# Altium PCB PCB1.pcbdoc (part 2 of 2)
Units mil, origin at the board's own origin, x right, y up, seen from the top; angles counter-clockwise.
Board outline 3200 x 1800 mil, 2 copper layers (Top Layer, Bottom Layer), stack 62.206 mil thick; 104 components, 97 nets, 542 pads, 186 vias.
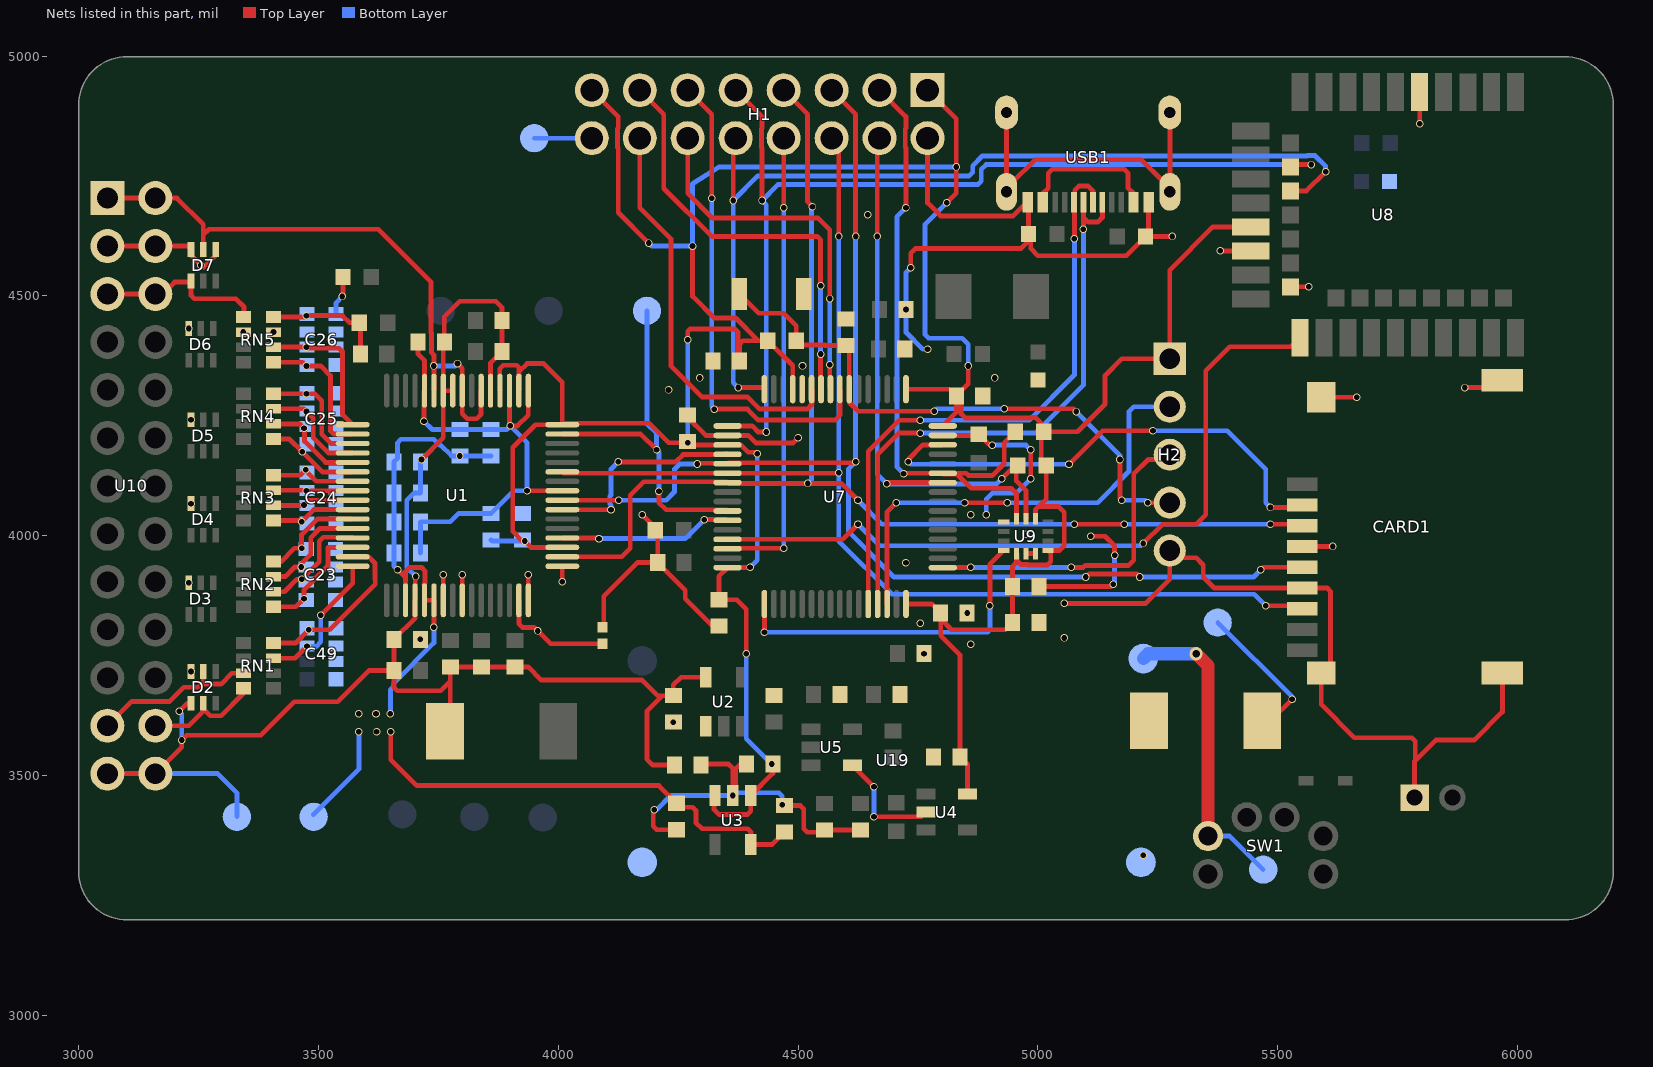
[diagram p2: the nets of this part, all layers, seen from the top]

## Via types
v1: diameter 15.75, hole 11.8, Top Layer to Bottom Layer, 184 vias
v2: diameter 19.68, hole 13.8, Top Layer to Bottom Layer, 1 vias
v3: diameter 27.56, hole 15.7, Top Layer to Bottom Layer, 1 vias

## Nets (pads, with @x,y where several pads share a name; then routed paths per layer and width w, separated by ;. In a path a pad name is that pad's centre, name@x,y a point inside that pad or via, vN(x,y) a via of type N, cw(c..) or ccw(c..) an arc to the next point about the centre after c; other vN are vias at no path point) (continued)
AGND: C5.1 C6.2 C11.1 C12.1 C13.2 C14.1 C15.1 C16.1 C17.1 C18.1 C19.1 C21.1 C22.1 C23.5 C23.6 C23.7 C23.8 C24.5 C24.6 C24.7 C24.8 C25.5 C25.6 C25.7 C25.8 C26.3 C26.5 C26.6 C26.7 C26.8 C29.1 C30.1 C31.1 C32.1 C33.1 C34.1 C49.5 C49.6 C49.7 C49.8 D2.3 D3.3 D4.3 D5.3 D6.3 D7.1 D7.3 R1.2 R13.1 RN5.2 RN5.7 U1.31 U1.33 U1.41 U1.49 U1.51 U1.60 U2.1 U3.2 U4.2 U5.4 U10.3 U10.4 U19.4 | length 2732.8
  Top Layer w10: U10.3@3060,4603.82 U10.4@3160,4603.82 3227.48,4603.82 D7.3@3234.41,4596.89 3234.41,4584.41 v1(3255,4563.82) ; v1@3260,4558.82 3285.59,4584.41 D7.1@3285.59,4596.89 ; v1(3550,4498.82) 3551.02,4499.84 R1.2@3551.02,4539.5 ; C6.2@3707.44,4393.82 3707.44,4379.47 3721.1,4365.81 U1.60@3721.1,4302.32 3720,4301.22 v1(3720,4238.82) ; U1.51@3898.27,4302.32 3898.27,4230.55 v1(3900,4228.82) 3915,4228.82 3937.5,4251.32 3937.5,4302.18 U1.49@3937.64,4302.32 ; U1.31@3917.95,3865.32 3917.95,3816.31 3925.44,3808.82 3950,3808.82 v1(3957.5,3801.32) 3984.08,3774.74 R13.1@4092.04,3774.74 ; v1(3935,4093.82) 3944.84,4093.82 3945,4093.66 U1.41@4008.5,4093.66 ; v1(4008.5,3903.82) U1.33@4008.5,3936.18 ; v1(4200,3428.82) 4197.93,3426.74 4197.93,3394.01 4205,3386.93 C16.1@4246.76,3386.93 ; C12.1@4297.57,3521.68 4299.7,3523.82 4355,3523.82 4364.2,3514.61 v1(4364.2,3458.24) 4370,3464.04 4370,3513.82 4380,3523.82 C17.1@4392.44,3523.82 ; C15.1@4471.76,3437.17 4505,3437.17 4512.07,3430.1 4512.07,3388.82 4519.14,3381.74 4550.49,3381.74 C21.1@4555,3386.26 C18.1@4630,3386.26 ; U5.4@4613.31,3521.41 v1(4658.23,3476.49) ; v1(4658.23,3413.82) 4756.69,3413.82 U4.2@4766.69,3423.82
  Bottom Layer w10: C26.5@3536.79,4461.97 3536.79,4485.6 v1(3550,4498.82) ; C32.1@3712.56,3963.82 C31.1@3712.56,4028.82 3775,4028.82 3792.56,4046.38 C29.1@3860,4046.38 3907.44,4093.82 v1(3935,4093.82) 3935,4193.82 v1(3900,4228.82) 3892.56,4221.38 C33.1@3860,4221.38 C34.1@3795,4221.38 3737.44,4221.38 v1(3720,4238.82) ; v1(4200,3428.82) 4205,3428.82 4234.42,3458.24 v1(4364.2,3458.24) 4369.78,3463.82 4460,3463.82 4467.07,3456.74 v1(4467.07,3438.82) ; v1(4658.23,3413.82) v1(4658.23,3476.49)
  other v1: 4240,3611.26 3234.41,3716.89 3712.56,3783.82 3229.41,3901.89 3234.41,4066.89 3234.41,4241.89 3343.5,4424.57 3406.5,4424.57 3229.41,4431.89
AVDD: AVDD.1 C15.2 C16.2 C27.2 C28.2 C31.2 C32.2 C33.2 C34.2 D7.2 U1.19 U1.21 U1.22 U1.54 U1.56 U1.59 U3.5 U10.1 U10.2 | length 3427.8
  Top Layer w10: U10.1@3060,4703.82 U10.2@3160,4703.82 3205,4703.82 3260,4648.82 3260,4626.95 ; D7.2@3260,4596.89 3260,4626.95 ; v1(3650.67,3591.06) 3650.67,3533.14 3705,3478.82 4210,3478.82 C16.2@4246.76,3442.05 4255,3433.82 4280,3433.82 4287.07,3426.74 4287.07,3401.74 4300,3388.82 4395,3388.82 4402.07,3381.74 4402.07,3356.34 U3.5@4401.6,3355.87 4445.58,3355.87 C15.2@4471.76,3382.05 ; v1(3665,3928.82) 3681.73,3912.09 ; U1.19@3681.73,3865.32 3681.73,3912.09 ; U1.21@3720,3898.82 3722.07,3900.89 3722.07,3926.74 3715,3933.82 3690,3933.82 3681.73,3925.55 3681.73,3912.09 ; U1.21@3721.1,3865.32 U1.22@3740.79,3865.32 v1(3740.79,3808.82) ; U1.59@3740.79,4302.32 v1(3740.79,4353.82) 3740.79,4376.59 3735.83,4381.55 3735.83,4422.99 3735,4423.82 3735,4528.82 3625,4638.82 3271.86,4638.82 3260,4626.95 ; v1(3790,4358.82) 3799.84,4348.98 U1.56@3799.84,4302.32 3799.84,4253.98 3810,4243.82 3830,4243.82 3839.21,4253.03 U1.54@3839.21,4302.32
  Bottom Layer w10: AVDD.1@3490,3418.82 3584.37,3513.18 v1(3584.37,3591.06) ; v1(3650,3628.82) 3650,3678.82 3657.01,3685.82 3657.01,3692.49 3740.79,3776.28 v1(3740.79,3808.82) ; v1(3665,3928.82) 3657.44,3936.38 C32.2@3657.44,3963.82 C31.2@3657.44,4028.82 C28.2@3657.44,4088.82 C27.2@3657.44,4153.82 3665,4161.38 3665,4193.82 3672.07,4200.89 3740,4200.89 3752.07,4188.82 3755,4188.82 3777.56,4166.26 v1(3795,4166.26) C33.2@3860,4166.26 ; v1(3740.79,4353.82) 3785,4353.82 v1(3790,4358.82)
  other v1: 3621.15,3591.06 3584.37,3628.82 3620,3628.82
AVSS: AVSS.1 C1.1 C2.1 C3.2 C4.2 C5.2 C6.1 C7.1 C8.1 C9.1 C12.2 C13.1 C27.1 C28.1 D2.4 U1.20 U1.23 U1.25 U1.32 U1.53 U1.57 U1.58 U2.5 U10.25 U10.26 | length 3424.3
  Top Layer w10: U10.25@3060,3503.82 U10.26@3160,3503.82 3215,3558.82 v1(3215,3573.82) 3225,3583.82 3380,3583.82 3450,3653.82 3540,3653.82 3605,3718.82 C9.1@3657.44,3718.82 ; v1(3210,3633.82) 3226.93,3650.75 D2.4@3234.41,3650.75 ; v1(3702.6,3914.96) 3702.01,3914.37 3702.01,3891.36 3702.6,3890.77 3702.6,3866.49 U1.20@3701.42,3865.32 3701.42,3827.8 C5.2@3657.44,3783.82 C9.1@3657.44,3718.82 ; v1(3715,4158.82) 3760.47,4204.29 U1.58@3760.47,4302.32 ; U1.23@3760.47,3865.32 v1(3760.47,3918.82) ; C1.1@3763.78,3591.93 3775,3603.15 3775,3696.74 ; U1.57@3780.16,4302.32 U1.58@3760.47,4302.32 ; U1.25@3799.84,3865.32 3800,3865.48 v1(3800,3918.82) ; U1.53@3858.9,4302.32 3858.9,4360.16 C4.2@3882.56,4383.82 C3.2@3882.56,4448.82 3882.56,4476.26 3870,4488.82 3795,4488.82 3762.56,4456.38 3762.56,4393.82 3760.47,4391.73 U1.58@3760.47,4302.32 ; U1.32@3937.64,3865.32 v1(3937.64,3918.82) ; C12.2@4242.45,3521.68 4197.14,3521.68 4185,3533.82 4185,3634.2 4217.18,3666.38 ; U2.5@4307.6,3705 4256.19,3705 4240,3688.82 C13.1@4240,3666.38 4217.18,3666.38 ; C9.1@3657.44,3718.82 3657.44,3683.82 3664.51,3676.74 3755,3676.74 3775,3696.74 ; 3775,3696.74 C7.1@3775,3726.26 C8.1@3840,3726.26 C2.1@3910,3726.26 3937.56,3726.26 3965,3698.82 4175,3698.82 4207.44,3666.38 4217.18,3666.38
  Bottom Layer w10: U10.26@3160,3503.82 3290,3503.82 3330,3463.82 AVSS.1@3330,3413.82 ; v1(3210,3633.82) 3215,3628.82 v1(3215,3573.82) ; v1(3702.6,3914.96) 3684.17,3933.38 3684.17,4073.82 3699.17,4088.82 C28.1@3712.56,4088.82 C27.1@3712.56,4153.82
BIAS: D7.4 RN5.1 U10.5 U10.6 | length 343.9
  Top Layer w10: U10.5@3060,4503.82 U10.6@3160,4503.82 3175,4503.82 3200,4528.82 3232.48,4528.82 D7.4@3234.41,4530.75 3234.41,4500.89 3241.48,4493.82 3327.93,4493.82 3345,4476.74 RN5.1@3345,4468.82
BIAS_DRV: C10.2 C26.4 R2.2 RN5.8 | length 252.1
  Top Layer w10: RN5.8@3406.5,4456.06 3472.24,4456.06 v1(3475,4458.82) 3550,4458.82 3565,4443.82 R2.2@3585.34,4443.82 3587.44,4441.72 C10.2@3587.44,4378.82
CS1: U1.39 U7.20 | length 444.9
  Top Layer w10: U1.39@4008.5,4054.29 4008.97,4053.82 v1(4110,4053.82) ; v1(4125,4153.82) 4245,4153.82 4260.19,4169.01 4346.63,4169.01 4347.76,4170.14 U7.20@4353.01,4170.14
  Bottom Layer w10: v1(4110,4053.82) 4110,4063.45 4107.28,4066.16 4107.28,4081.79 4110,4084.5 4110,4138.82 v1(4125,4153.82)
CS2: CARD1.2 U7.62 | length 1051.3
  Top Layer w10: v1(4730,4153.82) 4730,4158.82 4760.5,4189.32 U7.62@4801.83,4189.32 ; v1(5065,4148.82) 5135,4218.82 v1(5240,4218.82) ; v1(5485,4058.82) 5546.06,4058.82 CARD1.2@5551.34,4064.1
  Bottom Layer w10: v1(4730,4153.82) 4735,4148.82 v1(5065,4148.82) ; v1(5240,4218.82) 5395,4218.82 5475,4138.82 5475,4068.82 v1(5485,4058.82)
CS3: H1.8 U7.30 | length 972.4
  Top Layer w10: U7.30@4353.01,3972.78 4354.05,3973.82 v1(4470,3973.82) ; v1(4470,4683.82) H1.8@4470,4828.82
  Bottom Layer w10: v1(4470,3973.82) v1(4470,4683.82)
D+: U7.44 USB1.A6 USB1.B6 | length 1269.2
  Top Layer w10: U7.44@4646.32,3857.57 4646.32,4175.59 4711.29,4240.55 v1(4755,4240.55) ; v1(5076.14,4618.82) 5076.14,4694.64 USB1.B6@5075.47,4695.31 5077.01,4696.84 5077.01,4720.26 5085.57,4728.82 5105,4728.82 5114.85,4718.97 USB1.A6@5114.84,4695.31
  Bottom Layer w10: v1(4755,4240.55) 4981.73,4240.55 5076.14,4334.96 v1(5076.14,4618.82)
D-: U7.45 USB1.A7 USB1.B7 | length 1262
  Top Layer w10: U7.45@4666,3857.57 4666,4169.82 4710,4213.82 v1(4755,4213.82) ; v1(5095,4638.82) 5095,4663.82 ; USB1.A7@5095.15,4695.31 5095,4695.16 5095,4663.82 ; USB1.B7@5134.52,4695.31 5134.52,4663.34 5125,4653.82 5105,4653.82 5095,4663.82
  Bottom Layer w10: v1(4755,4213.82) 4995,4213.82 5095,4313.82 v1(5095,4638.82)
DRDY: TP_DRDY.1 U1.47 U7.26 | length 767.4
  Top Layer w10: U1.47@4008.5,4211.77 4172.05,4211.77 v1(4205,4178.82) ; v1(4210,4092.83) 4210,4068.82 4225,4053.82 U7.26@4350.72,4053.82
  Bottom Layer w10: TP_DRDY.1@4185,4468.82 4185,4233.82 4205,4213.82 v1(4205,4178.82) 4210,4173.82 v1(4210,4092.83)
DVDD: C17.2 C19.2 C29.2 C30.2 C40.2 C41.2 C42.2 C43.1 C44.1 C45.1 C46.1 C47.2 CARD1.4 DVDD.1 H1.1 H1.15 H2.1 R4.2 R9.2 R10.2 U1.35 U1.48 U1.50 U1.52 U3.1 U3.3 U4.5 U7.1 U7.13 U7.19 U7.32 U7.48 U7.64 U8.19 U9.5 U9.8 U9.12 | length 7907.1
  Top Layer w10: U1.52@3878.58,4302.32 3877.93,4302.97 3877.93,4348.04 3885,4355.12 3913.7,4355.12 3917.95,4350.87 3917.95,4341.77 ; U1.50@3917.95,4302.32 3917.95,4341.77 ; U1.35@4008.5,3975.55 3943.27,3975.55 v1(3930,3988.82) 3925,3988.82 3905,4008.82 3905,4183.82 3952.64,4231.46 U1.48@4008.5,4231.46 ; H1.15@4070,4928.82 4125,4873.82 4125,4849.46 4123.58,4848.04 4123.58,4809.59 4125,4808.17 4125,4673.82 v1(4188.76,4610.06) ; v1(4270,4408.82) 4270,4425.89 4275,4430.89 4367.93,4430.89 4375,4423.82 4375,4366.38 C47.2@4377.56,4363.82 4377.93,4364.18 4377.93,4399.44 4385,4406.52 4417.3,4406.52 ; v1(4280,4603.82) 4280,4498.82 4325,4453.82 4370,4453.82 4417.3,4406.52 ; U3.3@4326.8,3458.24 4325,3456.44 4325,3428.82 4335,3418.82 4395,3418.82 4401.6,3425.42 U3.1@4401.6,3458.24 4447.56,3504.2 C17.2@4447.56,3523.82 ; v1(4392.07,3753.82) 4392.07,3846.74 4372.44,3866.38 C44.1@4335,3866.38 4335,3915.4 U7.32@4353.01,3933.41 4353.42,3933.82 v1(4400,3933.82) ; v1@4415,4170.4 4411.58,4173.82 4396.34,4173.82 4380.83,4189.32 U7.19@4353.01,4189.32 4271.94,4189.32 4270,4191.26 4267.44,4193.82 4230,4193.82 4189.48,4234.33 4011.38,4234.33 U1.48@4008.5,4231.46 ; U7.13@4488.84,4305.46 4488.84,4354.76 R4.2@4437.08,4406.52 4417.3,4406.52 ; U7.48@4725.06,3857.57 4778.69,3857.57 C46.1@4797.44,3838.82 ; U7.1@4725.06,4305.46 4815.92,4305.46 C43.1@4830,4291.38 ; H1.1@4770,4928.82 4830,4868.82 v1(4830,4768.82) 4830,4713.82 v1(4810,4693.82) ; U7.64@4801.83,4228.69 4830,4256.86 C43.1@4830,4291.38 ; U4.5@4853.31,3461.22 4853.31,3523.07 C19.2@4837.56,3538.82 4837.56,3751.26 4797.44,3791.38 4797.44,3826.38 4820,3803.82 4932.44,3803.82 C42.2@4947.44,3818.82 C41.2@4947.44,3893.82 4947.44,3936.26 4955.32,3944.14 U9.5@4955.32,3962.59 4957.01,3960.91 4957.01,3947.93 4965.14,3939.8 4978.12,3939.8 4979.1,3938.82 5020,3938.82 5027.07,3945.89 5027.07,3963.27 U9.8@5021.06,3969.28 5045.47,3969.28 5055,3978.82 5055,4048.82 5042.93,4060.89 5002.07,4060.89 ; v1(4855,4353.82) 4855,4316.38 C43.1@4830,4291.38 ; U9.12@4994.69,4035.04 4995,4035.34 4995,4053.82 5002.07,4060.89 ; R9.2@5007.42,4146.18 5007.08,4146.52 5007.08,4216.52 R10.2@5012.08,4216.52 ; R9.2@5017.42,4146.18 5017.42,4076.24 5002.07,4060.89 ; U8.19@5443.82,4643.82 5365,4643.82 5275,4553.82 H2.1@5275,4368.82 5175,4368.82 5140,4333.82 5140,4273.82 5082.7,4216.52 R10.2@5012.08,4216.52 ; C40.2@5468.11,3613.82 5485,3613.82 v1(5530,3658.82) ; CARD1.4@5551.34,3977.48 v1(5615,3977.48) ; 3917.95,4341.77 3935,4358.82 3970,4358.82 4008.5,4320.32 U1.48@4008.5,4231.46 ; C43.1@4830,4291.38 4840,4281.38 4840,4253.82 4848.27,4245.55 4984.13,4245.55 4985,4246.41 4995,4246.41 5012.08,4229.33 R10.2@5012.08,4216.52
  Bottom Layer w10: C29.2@3860,3991.26 3862.44,3988.82 v1(3930,3988.82) ; v1(4188.76,4610.06) 4195,4603.82 v1(4280,4603.82) 4280,4733.82 4335,4768.82 v1(4830,4768.82) ; v1(4270,4193.82) v1(4270,4408.82) ; v1(4392.07,3753.82) 4392.07,3576.74 v1(4445,3523.82) ; v1(4400,3933.82) 4415,3948.82 v1@4415,4170.4 ; v1(4810,4693.82) 4765,4648.82 4765,4418.82 4772.07,4411.74 4842.07,4411.74 4855,4398.82 v1(4855,4353.82) ; DVDD.1@5375,3818.82 5530,3663.82 v1(5530,3658.82)
  other v1: 4415,4171.01
G1: H1.11 U7.8 | length 1018
  Top Layer w10: H1.11@4270,4928.82 4320,4878.82 v1(4320,4703.82) ; v1(4325,4263.82) 4394.56,4263.82 4417.29,4241.08 4577.26,4241.08 4587.26,4251.08 U7.8@4587.26,4305.46
  Bottom Layer w10: v1(4320,4703.82) 4320,4268.82 v1(4325,4263.82)
G2: H1.12 U7.9 | length 775.5
  Top Layer w10: H1.12@4270,4828.82 4270,4713.82 4321.67,4662.15 4541.67,4662.15 4565.93,4637.89 v1(4565.93,4494.42) ; v1(4565.93,4356.65) 4565.93,4307.12 U7.9@4567.58,4305.46
  Bottom Layer w10: v1(4565.93,4356.65) v1(4565.93,4494.42)
G3: H1.13 U7.10 | length 908.8
  Top Layer w10: H1.13@4170,4928.82 4220,4878.82 4220,4723.82 4320,4623.82 4540,4623.82 4547.07,4616.74 v1(4547.07,4521.11) ; v1(4547.07,4378.62) 4547.07,4306.28 U7.10@4547.89,4305.46
  Bottom Layer w10: v1(4547.07,4378.62) v1(4547.07,4521.11)
G4: H1.14 U7.11 | length 869.4
  Top Layer w10: H1.14@4170,4828.82 4170,4683.82 4235,4618.82 4235,4353.82 4300,4288.82 4395,4288.82 4420,4263.82 4519.08,4263.82 4529.08,4273.82 4529.08,4304.6 U7.11@4528.21,4305.46
GND: C35.2 C36.2 C37.2 C38.2 C39.2 C40.1 C41.1 C42.1 C43.2 C44.2 C45.2 C46.2 C47.1 CARD1.6 CARD1.10 CARD1.11 CARD1.12 CARD1.13 GND.1 H1.2 H1.16 H2.5 LED2.1 LED3.1 R3.2 R5.2 R6.1 R7.1 R13.2 SW2.2 U6.1 U7.12 U7.18 U7.63 U8.5 U8.21 U8.24 U9.1 U9.6 U9.7 U19.2 USB1.A1B12 USB1.B1A12 | length 4871.7
  Top Layer w10: R13.2@4092.04,3808.82 4095,3811.78 4095,3873.82 4165,3943.82 C35.2@4207.44,3943.82 ; v1(4175,4043.82) 4202.42,4016.39 R5.2@4202.42,4011.18 4207.44,4006.16 C35.2@4207.44,3943.82 ; C45.2@4270,4246.38 4307.38,4209 U7.18@4353.01,4209 4396.08,4209 4411.72,4193.36 4489.55,4193.36 v1(4500,4203.82) ; C44.2@4335,3811.26 4322.56,3811.26 4265,3868.82 4265,3886.26 C35.2@4207.44,3943.82 ; v1(4735,4558.82) 4735,4588.82 4745,4598.82 4965,4598.82 4980.34,4614.16 R7.1@4980.34,4628.82 ; H1.2@4770,4828.82 4770,4693.82 4797.21,4666.61 4948.24,4666.61 4976.95,4695.31 USB1.B1A12@4979.01,4695.31 4980.34,4693.99 R7.1@4980.34,4628.82 ; U7.63@4801.83,4209 4874.57,4209 R3.2@4877.08,4211.52 4899.78,4188.82 v1(4905,4188.82) ; U9.6@4975,3962.59 U9.7@4994.69,3962.59 ; v1(4985,4118.82) v1(4985,4178.82) ; C41.1@5002.56,3893.82 5152.29,3893.82 v1(5157.28,3898.81) ; v1(5055,3858.82) 5225,3858.82 5275,3908.82 H2.5@5275,3968.82 5290,3953.82 5330,3953.82 5345,3938.82 5345,3913.82 5367.95,3890.87 CARD1.6@5551.34,3890.87 5602.95,3890.87 5610,3883.82 5610,3732.99 CARD1.10@5590.71,3713.7 5590.71,3648.11 5660,3578.82 5780,3578.82 5787.07,3571.74 5787.07,3530.89 ; v1(5110,3998.82) 5140,3998.82 5160,3978.82 v1(5160,3958.82) ; USB1.A1B12@5230.98,4695.31 5230.98,4630.14 R6.1@5224.66,4623.82 ; v1(5280,4623.82) R6.1@5224.66,4623.82 ; v1(5380,4593.82) U8.21@5443.82,4593.82 ; U8.24@5526.5,4518.82 v1(5565,4518.82) ; CARD1.13@5590.71,4288.51 v1(5665,4288.51) ; U6.1@5785.63,3453.82 5785.63,3529.45 5787.07,3530.89 ; v1(5796.18,4858.82) U8.5@5796.18,4924.92 ; v1(5890,4308.82) 5953.54,4308.82 CARD1.12@5968.66,4323.94 ; CARD1.11@5968.66,3713.7 5968.66,3632.48 5910,3573.82 5830,3573.82 5787.07,3530.89 ; R7.1@4980.34,4628.82 4985,4624.16 4985,4598.82 5000,4583.82 5184.66,4583.82 R6.1@5224.66,4623.82
  Bottom Layer w10: GND.1@3950,4828.82 H1.16@4070,4828.82 ; v1(4735,4558.82) 4725.22,4549.04 v1(4725.22,4471.4) 4725.22,4423.59 4760,4388.82 v1(4770,4388.82) ; v1(4892.32,4043.82) 4892.32,4076.14 4905,4088.82 4955,4088.82 v1(4985,4118.82) ; v1(4905,4188.82) 4975,4188.82 v1(4985,4178.82) ; v1(5157.28,3898.81) 5160,3901.53 v1(5160,3958.82)
  other v1: 5220,3333.82 4762.56,3753.82 4860,3773.82 5055,3786.71 4755,3817.67 4852.56,3838.82 4725,3943.82 4975,4002.67 4860,4043.82 4230,4303.82 4295,4328.82 4910,4328.82 4509.35,4353.82 4645,4668.82
I2C1_SCL: H1.4 R9.1 U7.58 U9.13 | length 1248.6
  Top Layer w10: v1(4665,4623.82) 4665,4823.82 H1.4@4670,4828.82 ; v1(4685,4107.97) 4687.61,4110.58 U7.58@4801.83,4110.58 ; v1(4925,4118.82) 4950.23,4144.05 4955,4139.28 4955,4114.26 4975,4094.26 U9.13@4975,4035.04
  Bottom Layer w10: v1(4665,4623.82) 4665,4127.97 v1(4685,4107.97) 4914.15,4107.97 v1(4925,4118.82)
I2C1_SDA: H1.3 R10.1 U7.59 U9.14 | length 1359.5
  Top Layer w10: H1.3@4670,4928.82 4725,4873.82 4725,4849.46 4723.58,4848.04 4723.58,4809.59 4725,4808.17 v1(4725,4683.82) ; v1(4720,4129.44) 4720.82,4130.26 U7.59@4801.83,4130.26 ; R10.1@4952.76,4216.52 4930,4193.75 4930,4150.49 4904.85,4125.34 4855.53,4125.34 4850.6,4130.26 U7.59@4801.83,4130.26 ; U9.14@4955.32,4035.04 4955.32,4063.23 4955.46,4063.36 4955.46,4088.36 4945,4098.82 4861.11,4098.82 4831.35,4128.57 4803.52,4128.57 U7.59@4801.83,4130.26
  Bottom Layer w10: v1(4720,4129.44) 4706.11,4143.33 4706.11,4664.93 v1(4725,4683.82)
IN1N: C49.4 RN1.8 U1.15 | length 359.2
  Top Layer w10: RN1.8@3406.5,3776.06 3452.24,3776.06 v1(3480,3803.82) 3523.66,3803.82 3618.61,3898.76 3618.61,3908.76 3617.92,3909.45 3617.92,3943.01 3605.06,3955.87 U1.15@3571.5,3955.87
IN1P: C49.3 RN1.7 U1.16 | length 298.2
  Top Layer w10: RN1.7@3406.5,3744.57 3451.16,3744.57 v1(3476.16,3769.57) ; v1(3505,3833.82) 3571.5,3900.32 U1.16@3571.5,3936.18
  Bottom Layer w10: v1(3476.16,3769.57) 3476.91,3768.82 3495,3768.82 3505,3778.82 v1(3505,3833.82)
IN2N: C23.2 RN2.6 U1.13 | length 237.4
  Top Layer w10: RN2.6@3406.5,3883.07 3429.25,3883.07 3455,3908.82 v1(3465,3908.82) 3501.85,3945.67 3501.85,3988.11 3510.33,3996.59 3570.15,3996.59 U1.13@3571.5,3995.24
IN2P: C23.1 RN2.5 U1.14 | length 249.7
  Top Layer w10: RN2.5@3406.5,3851.58 3452.76,3851.58 v1(3470,3868.82) 3470,3887.15 3519.84,3936.99 3519.84,3975.55 U1.14@3571.5,3975.55
IN3N: C23.4 RN2.8 U1.11 | length 218.3
  Top Layer w10: RN2.8@3406.5,3946.06 3422.24,3946.06 3450,3973.82 v1(3465,3973.82) 3465,4002.15 3497.46,4034.61 U1.11@3571.5,4034.61
IN3P: C23.3 RN2.7 U1.12 | length 230.7
  Top Layer w10: RN2.7@3406.5,3914.57 3430.75,3914.57 3450.83,3934.65 v1(3464.17,3934.65) 3464.17,3941.31 3483.86,3961 3483.86,3995.56 3503.21,4014.92 U1.12@3571.5,4014.92
IN4N: C24.2 RN3.6 U1.9 | length 169.5
  Top Layer w10: RN3.6@3406.5,4063.07 3469.25,4063.07 v1(3470,4063.82) 3480.16,4073.98 U1.9@3571.5,4073.98
IN4P: C24.1 RN3.5 U1.10 | length 176.7
  Top Layer w10: RN3.5@3406.5,4031.58 3462.24,4031.58 v1(3465,4028.82) 3490.47,4054.29 U1.10@3571.5,4054.29
IN5N: C24.4 RN3.8 U1.7 | length 181.3
  Top Layer w10: RN3.8@3406.5,4126.06 3462.24,4126.06 v1(3473.76,4137.57) 3473.76,4135.06 3495.47,4113.35 U1.7@3571.5,4113.35
IN5P: C24.3 RN3.7 U1.8 | length 165.4
  Top Layer w10: RN3.7@3406.5,4094.57 3474.09,4094.57 v1(3475,4093.66) U1.8@3571.5,4093.66
IN6N: C25.2 RN4.6 U1.5 | length 213.7
  Top Layer w10: RN4.6@3406.5,4233.07 3460.75,4233.07 v1(3470,4223.82) 3471.11,4222.71 3471.11,4196.48 3514.87,4152.72 U1.5@3571.5,4152.72
IN6P: C25.1 RN4.5 U1.6 | length 193.4
  Top Layer w10: RN4.5@3406.5,4201.58 3439.34,4201.58 v1(3466.05,4174.87) 3507.89,4133.03 U1.6@3571.5,4133.03
IN7N: C25.4 RN4.8 U1.3 | length 249.3
  Top Layer w10: RN4.8@3406.5,4296.06 v1(3475,4296.06) 3492.76,4296.06 3507.09,4281.73 3507.09,4211.38 3526.39,4192.09 U1.3@3571.5,4192.09
IN7P: C25.3 RN4.7 U1.4 | length 227.1
  Top Layer w10: RN4.7@3406.5,4264.57 3469.25,4264.57 v1(3475,4258.82) 3489.1,4244.72 3489.1,4203.93 3520.63,4172.4 U1.4@3571.5,4172.4
IN8N: C26.2 RN5.6 U1.1 | length 308.6
  Top Layer w10: RN5.6@3406.5,4393.07 v1(3475,4393.07) 3477.18,4390.89 3542.93,4390.89 3550,4383.82 3550,4252.96 U1.1@3571.5,4231.46
IN8P: C26.1 RN5.5 U1.2 | length 294.4
  Top Layer w10: RN5.5@3406.5,4361.58 3467.24,4361.58 v1(3475,4353.82) 3505,4353.82 3525.08,4333.73 3525.08,4218.84 3532.15,4211.77 U1.2@3571.5,4211.77
INT1: U7.33 U9.4 | length 708.4
  Top Layer w10: U7.33@4429.78,3857.57 4429.78,3799.03 v1(4430,3798.82) ; v1(4900,3853.82) 4900,3940.34 U9.4@4928.94,3969.28
  Bottom Layer w10: v1(4430,3798.82) 4895,3798.82 4900,3803.82 v1(4900,3853.82)
MISO: CARD1.7 H1.6 U1.43 U7.22 | length 2449.1
  Top Layer w10: U1.43@4008.5,4133.03 4011.27,4130.26 U7.22@4353.01,4130.26 4584.04,4130.26 v1(4585,4131.22) ; H1.6@4570,4828.82 4585,4813.82 v1(4585,4623.82) ; v1(5475,3853.82) 5545.08,3853.82 CARD1.7@5551.34,3847.56
  Bottom Layer w10: v1(4585,4623.82) v1(4585,4131.22) 4585,3988.82 4696.14,3877.67 5451.14,3877.67 v1(5475,3853.82)
MOSI: CARD1.3 H1.7 U1.34 U7.23 | length 2556.6
  Top Layer w10: U1.34@4008.5,3955.87 4132.05,3955.87 4150,3973.82 4150,4083.82 4178.45,4112.27 U7.23@4351.33,4112.27 ; U7.23@4353.01,4110.58 4354.78,4108.82 v1(4520,4108.82) 4590,4108.82 v1(4625,4073.82) ; H1.7@4470,4928.82 4520,4878.82 4520,4696.01 v1(4530,4686.01) ; v1(5075.98,4023.82) v1(5180.02,4023.82) ; v1(5485,4023.82) 5548.31,4023.82 CARD1.3@5551.34,4020.79
  Bottom Layer w10: v1(4520,4108.82) 4528.21,4117.03 4528.21,4684.22 v1(4530,4686.01) ; v1(4625,4073.82) 4675,4023.82 v1(5075.98,4023.82) ; v1(5180.02,4023.82) v1(5485,4023.82)
NRST: C39.1 H2.4 R4.1 SW2.1 U7.7 | length 1217.5
  Top Layer w10: SW2.1@4378.07,4503.82 4418.07,4463.82 4470,4463.82 4496.4,4437.41 R4.1@4496.4,4406.52 4505.44,4397.48 4554.88,4397.48 4556.1,4396.26 C39.1@4600,4396.26 4606.95,4389.3 U7.7@4606.95,4305.46 4606.95,4277.63 4625.18,4259.41 v1(4783.76,4259.41) ; v1(4929.93,4264.41) 5074.41,4264.41 v1(5080,4258.82) ; v1(5171.14,4158.82) 5171.14,4077.67 v1(5175,4073.82) ; v1(5228.86,4068.82) H2.4@5275,4068.82
  Bottom Layer w10: v1(4783.76,4259.41) 4788.76,4264.41 v1(4929.93,4264.41) ; v1(5080,4258.82) 5171.14,4167.67 v1(5171.14,4158.82) ; v1(5175,4073.82) 5223.86,4073.82 v1(5228.86,4068.82)
RAW: RAW.1 SW1.4 U19.1 | length 648.7
  Top Layer w27.56: v3(5330,3753.82) 5354.92,3728.89 SW1.4@5354.92,3373.5
  Bottom Layer w10: SW1.4@5354.92,3373.5 5400.31,3373.5 RAW.1@5470,3303.82
  Bottom Layer w27.56: U19.1@5219.97,3743.78 5230,3753.82 v3(5330,3753.82)
RESET: U1.36 U7.27 | length 362.1
  Top Layer w10: U1.36@4008.5,3995.24 4083.58,3995.24 v1(4085,3993.82) ; v1(4304.59,4033.4) 4351.45,4033.4 U7.27@4353.01,4031.84
  Bottom Layer w10: v1(4085,3993.82) 4265,3993.82 v1(4304.59,4033.4)
RST: U7.29 U8.26 | length 1580.4
  Top Layer w10: U7.29@4353.01,3992.47 4461.98,3992.47 4462.19,3992.67 4477.81,3992.67 4478.02,3992.47 4593.65,3992.47 v1(4625,4023.82) ; v1(5220,3983.82) 5260,4023.82 5330,4023.82 5350,4043.82 5350,4343.82 5400,4393.82 5527.28,4393.82 U8.26@5546.18,4412.72
  Bottom Layer w10: v1(4625,4023.82) 4670,3978.82 5215,3978.82 v1(5220,3983.82)
SBR1: D2.5 RN1.4 U10.24 | length 246.7
  Top Layer w10: U10.24@3160,3603.82 3230,3603.82 3260,3633.82 ; D2.5@3260,3650.75 3260,3633.82 ; RN1.4@3343.5,3681.58 3343.5,3670.88 3297.03,3624.41 3274.15,3624.41 3264.74,3633.82 3260,3633.82
SBR2: D2.2 RN1.3 U10.23 | length 354.5
  Top Layer w10: U10.23@3060,3603.82 3110.71,3654.52 3190,3654.52 3219.29,3683.82 3250,3683.82 3260,3693.82 ; D2.2@3260,3716.89 3260,3693.82 ; RN1.3@3343.5,3713.07 3319.55,3713.07 3297.03,3690.55 3263.27,3690.55 3260,3693.82
SCLK: CARD1.5 H1.5 U1.40 U7.21 | length 2618.8
  Top Layer w10: U1.40@4008.5,4073.98 v1(4126.14,4073.98) ; v1(4290,4149.42) 4291.6,4151.02 4351.95,4151.02 U7.21@4353.01,4149.95 4355.21,4152.15 v1@4620,4152.15 ; H1.5@4570,4928.82 4620,4878.82 v1(4620,4623.82) ; v1(5100,3913.82) 5106.14,3919.96 5206.5,3919.96 v1(5212.64,3913.82) ; v1(5465,3928.82) 5470.36,3934.18 CARD1.5@5551.34,3934.18
  Bottom Layer w10: v1(4126.14,4073.98) 4225.16,4073.98 4242.42,4091.24 4242.42,4138.82 4253.03,4149.42 v1(4290,4149.42) ; v1(4620,4623.82) v1(4620,4153.82) 4605,4138.82 4605,4008.82 4700,3913.82 v1(5100,3913.82) ; v1(5212.64,3913.82) 5450,3913.82 v1(5465,3928.82)
SHIELD: USB1.13 USB1.14 | length 733.6
  Top Layer w10: USB1.14@4934.72,4882.32 USB1.14@4934.72,4716.97 4946.01,4728.25 4946.01,4735.5 4994.33,4783.82 5215.66,4783.82 5260,4739.48 5260,4733.82 USB1.13@5275.27,4718.54 ; USB1.13@5275.27,4716.96 USB1.13@5275.27,4718.54 ; USB1.13@5275.27,4882.32 USB1.13@5275.27,4718.54
SWCLK: H2.3 U7.49 | length 676.1
  Top Layer w10: U7.49@4801.83,3933.41 4802.24,3933.82 v1(4860,3933.82) ; v1(5070,3933.82) 5094.56,3933.82 5098.69,3937.95 5189.13,3937.95 5200,3948.82 5200,4128.82 5230,4158.82 5265,4158.82 H2.3@5275,4168.82
  Bottom Layer w10: v1(4860,3933.82) v1(5070,3933.82)
SWDIO: H2.2 U7.46 | length 945.3
  Top Layer w10: U7.46@4685.69,3857.57 4685.69,4049.51 v1(4705,4068.82) ; v1(4847.13,4068.82) v1(4936.02,4068.82)
  Bottom Layer w10: v1(4705,4068.82) v1(4847.13,4068.82) ; v1(4936.02,4068.82) 5125,4068.82 5190,4133.82 5190,4258.82 5200,4268.82 H2.2@5275,4268.82
UART_RX: H1.10 U7.16 U8.16 | length 1975.3
  Top Layer w10: v1(4365,4698.82) 4365,4823.82 H1.10@4370,4828.82 ; v1(4375,4308.82) 4426.43,4308.82 U7.16@4429.78,4305.46 ; U8.16@5526.5,4718.82 5560,4718.82 v1(5600,4758.82)
  Bottom Layer w10: v1(4375,4308.82) 4365,4318.82 v1(4365,4698.82) 4416.14,4749.96 4856.58,4749.96 4864.08,4757.46 4864.08,4771.27 4884.62,4791.81 5561.32,4791.81 5562.19,4792.67 5577.81,4792.67 5600,4770.49 v1(5600,4758.82)
UART_TX: H1.9 U7.17 U8.14 | length 2062.6
  Top Layer w10: U7.17@4353.01,4228.69 4404.24,4228.69 4416.8,4216.13 v1(4433.91,4216.13) ; H1.9@4370,4928.82 4425,4873.82 4425,4849.46 4423.58,4848.04 4423.58,4809.59 4425,4808.17 v1(4425,4698.82) ; U8.14@5526.5,4768.82 5531.5,4773.82 v1(5570,4773.82)
  Bottom Layer w10: v1(4433.91,4216.13) 4433.91,4689.91 v1(4425,4698.82) 4458.15,4731.97 4875,4731.97 4882.07,4739.04 4882.07,4763.82 4892.07,4773.82 v1(5570,4773.82)
USB_VBUS: USB1.A4B9 USB1.B4A9 | length 285.1
  Top Layer w10: USB1.B4A9@5010.51,4695.31 5010.51,4713.47 5021.81,4724.77 5021.81,4755.62 5030,4763.82 5180,4763.82 5188.18,4755.63 5188.18,4724.77 USB1.A4B9@5199.57,4713.38
pads on no net: CARD1.1 CARD1.8 CARD1.CD D2.6 D3.6 D4.6 D5.6 D6.1 D6.6 D7.5 D7.6 SW1.1 SW1.3 SW1.5 SW1.6 U1.27 U1.29 U1.37 U1.38 U1.42 U1.44 U1.45 U1.46 U3.4 U4.4 U7.3 U7.4 U7.14 U7.15 U7.24 U7.25 U7.34 U7.35 U7.36 U7.37 U7.38 U7.39 U7.40 U7.41 U7.42 U7.43 U7.50 U7.51 U7.52 U7.53 U7.54 U7.55 U7.56 U7.57 U7.61 U8.1 U8.2 U8.3 U8.4 U8.7 U8.8 U8.9 U8.10 U8.11 U8.12 U8.13 U8.15 U8.17 U8.18 U8.20 U8.22 U8.23 U8.25 U8.27 U8.28 U8.29 U8.30 U8.31 U8.32 U8.33 U8.34 U8.35 U8.36 U8.37 U8.38 U8.39 U8.40 U8.41 U8.42 U8.43 U9.2 U9.3 U9.9 U9.10 U9.11 USB1.A8 USB1.B8

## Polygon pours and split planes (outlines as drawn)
AGND on Bottom Layer (solid, remove dead copper, pour order 16): 3515,4483.82 3550,4483.82 3555,4478.82 3555,3683.82 3518.25,3683.82 3518.25,4480.57
+5V on Bottom Layer (solid, remove dead copper, pour order 18): 4443.81,3398.58 4449.69,3403.5 4445,3403.82 4443.83,3404.99 4443.83,3428.17 4503.07,3428.17 4505,3430.1 4505,3458.82 4525,3478.82 4605,3478.82 4617.04,3466.77 4617.04,3417.78 4597.84,3398.58
+5V on Bottom Layer (solid, remove dead copper, pour order 20): 4443.83,3428.17 4499.72,3428.17 4499.72,3453.54 4525,3478.82 4605,3478.82 4616.92,3466.89 4616.92,3417.78 4597.66,3398.53 4443.81,3398.53 4443.83,3398.54
AVDD on Top Layer (solid, remove dead copper, pour order 0): 3794.84,4253.98 3795.79,4253.03 3834.21,4253.03 3840,4247.24 3840,4208.82 3859.91,4208.82 3879.38,4186.82 3879.38,4142.66 3775,4143.82 3770,4148.82 3770,4183.82 3794.84,4208.66
AVSS on Bottom Layer (solid, remove dead copper, pour order 22): 3685,3933.82 3948.26,3934.07 3948.26,3832.08 3945.09,3828.82 3685,3828.82
AGND on Bottom Layer (solid, remove dead copper, pour order 24): 3120,4638.82 3297.57,4638.82 3315,4621.39 3315,3618.82 3300,3603.82 3214.4,3603.82 3200,3618.22 3200,4563.82 3120,4563.82
AGND on Bottom Layer (solid, remove dead copper, pour order 26): 3311.2,4443.8 3311.27,4443.87 3315.05,4443.87 3314.98,4443.8
AGND on Bottom Layer (solid, remove dead copper, pour order 28): 3310,4438.82 3314.98,4443.8 3535,4443.8 3535,4408.09 3310.73,4408.09 3310,4408.82
AVDD on Top Layer (solid, remove dead copper, pour order 2): 3550,3563.82 3550,3658.94 3692.19,3658.94 3692.19,3563.82
AGND on Top Layer (solid, remove dead copper, pour order 4): 4180,3343.82 4180,3724.92 4181.83,3723.09 4879.92,3723.09 4895,3708.02 4895,3353.82 4890,3353.82 4825,3288.82 4235,3288.82
+5V on Bottom Layer (solid, remove dead copper, pour order 30): 4347.44,3686.38 4375,3658.82 4375,3581.91 4496.15,3460.76 4569.12,3460.76 4582.95,3446.93 4582.95,3413.82 4439.2,3413.82 4280,3573.02 4281.29,3634.2 4185,3634.2 4185,3653.82 4217.56,3686.38
GND on Bottom Layer (solid, remove dead copper, pour order 32): 4870,4348.82 4950,4348.82 4946.46,4345.28 4946.46,4163.82 4875,4163.82 4870,4168.82
GND on Bottom Layer (solid, remove dead copper, pour order 34): 4725.45,4342.9 4910,4342.9 4910,4168.82 4905,4163.82 4730,4163.82 4725.45,4168.36
GND on Bottom Layer (solid, remove dead copper, pour order 36): 4005.54,4878.82 4113.62,4878.82 4113.62,4850.19 4120,4843.82 4120,4793.82 4395.76,4518.06 4395.76,4278.82 4155,4278.82 4135,4298.82 4135,4613.82 4010,4738.82 4010,4874.35
GND on Top Layer (solid, remove dead copper, pour order 6): 4193.82,3815.07 4203.93,4578.43 4767.43,4578.43 4767.43,4425.18 5079.11,4425.18 5085.32,3753.82 4255.08,3753.82
GND on Bottom Layer (solid, remove dead copper, pour order 38): 4725.22,4444.2 4929.62,4444.2 4930,4443.82 4930,4318.82 4724.35,4318.82 4724.35,4443.33
GND on Bottom Layer (solid, remove dead copper, pour order 40): 4661,4078.32 4666.5,4083.82 5070,4083.82 5133.92,4010.7 5133.92,3738.82 4645,3738.82 4661,3754.82
DVDD on Bottom Layer (solid, remove dead copper, pour order 42): 5195,4423.82 5196.55,4422.27 5381.55,4422.27 5495,4308.82 5495,4183.82 5610,4183.82 5660,4133.82 5660,3658.82 5585,3658.82 5540,3613.82 5540,3518.82 5523.95,3502.77 5427.07,3502.77 5427.07,4276.74 5390,4313.82 5195,4313.82
GND on Bottom Layer (solid, remove dead copper, pour order 44): 5515,4213.82 5515,4313.82 5370,4458.82 5370,4508.82 5360,4518.82 5155,4518.82 5125,4548.82 5125,4813.66 5143.01,4831.67 5347.85,4831.67 5395,4878.82 5395,4963.82 5410,4978.82 5815,4978.82 5821.33,4972.49 5821.33,4690.15 5775,4643.82 5765,4653.82 5635,4653.82 5585,4603.82 5585,4378.82 6040,4378.82 6050,4368.82 6050,4288.82 6035,4273.82 5962.84,4273.82 5892.96,4203.94 5524.88,4203.94
GND on Bottom Layer (solid, remove dead copper, pour order 46): 4130,3977.72 4130,4293.82 4135,4288.82 4308.4,4288.82 4320.2,4277.02 4320.2,3973.82 4133.9,3973.82
GND on Bottom Layer (solid, remove dead copper, pour order 48): 4472.45,4718.82 4687.08,4718.82 4704.89,4701.01 4704.89,4163.7 4700,4158.82 4266.05,4158.82 4250.86,4174.01 4250.86,4474.67 4275,4498.82 4345,4583.82
GND on Top Layer (solid, remove dead copper, pour order 8): 4568.42,4723.82 4685,4723.82 4700,4708.82 4700,4564.91 4683.62,4548.53 4565.93,4548.53 4565.93,4721.32
GND on Top Layer (solid, remove dead copper, pour order 10): 5075,3808.82 5285,3808.82 5290,3803.82 5290,3278.82 5285,3273.82 5070,3273.82 5060,3263.82 5035,3288.82 5035,3783.82 5058.82,3807.64 5073.82,3807.64
AGND on Bottom Layer (solid, remove dead copper, pour order 50): 3510,4593.82 4000,4593.82 4035,4558.82 4035,3638.82 4010,3613.82 3520,3613.82 3515,3608.82 3510,3613.82
AGND on Top Layer (solid, remove dead copper, pour order 12): 3564.34,3886.14 3564.34,4317.02 3586.14,4338.82 3590,4338.82 3597.02,4345.83 4008.5,4345.83 4025.7,4328.63 4025.7,3865.32 3585.16,3865.32
AGND on Bottom Layer (solid, remove dead copper, pour order 52): 4010,3793.82 4189.89,3793.82 4264.38,3719.32 4264.38,3689.97 4280,3674.35 4280,3328.12 4019.3,3328.12 4015,3323.82 4015,3788.82
GND on Top Layer (solid, remove dead copper, pour order 14): 5515,3778.82 5575,3778.82 5585,3768.82 6040,3768.82 6060,3748.82 6060,3638.82 6040,3638.82 5943.11,3541.93 5943.11,3416.58 5697.23,3416.58 5680,3433.82 5680,3508.82 5675,3513.82 5515,3513.82

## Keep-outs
Board Outline Layer:
  the board outline again, w10

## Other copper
Top Layer:
  drawing of 752 lines, arcs and shapes, not listed
  text "ChenJiaqi EEG V1" at 3040,4798.82 h120
Bottom Layer:
  drawing of 165 lines, arcs and shapes, not listed

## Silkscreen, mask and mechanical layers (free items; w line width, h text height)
Top Silkscreen Layer:
  text "ADS1299" at 3555,4593.82 h120
  text "STM32" at 4355,4573.82 h120
  text "SD CARD" at 5640,3563.82 h120
  text "POWER SUPPLY" at 4265,3203.82 h120
Bottom Silkscreen Layer:
  drawing of 135 lines, arcs and shapes, not listed
  text "BLUETOOTH" at 6055,4548.82 h120
  text "DRDY" at 4245,4523.82 h45
  text "VREF=VREFP-VREFN" at 5125,4438.82 h80
  text "VCAP1=AVSS+1.2V" at 5125,4338.82 h80
  text "VCAP2=(AVDD+AVSS)/2" at 5130,4248.82 h80
  text "VCAP3=AVDD+1.9V" at 5130,4153.82 h80
  text "VCAP4=(VREFP+VREFN)/2" at 5135,4058.82 h80
  text "VOUT / =5V" at 4431.2,3825.42 h70.87 r90
  text "VIN" at 5158.15,3822.22 h70.87 r90
  text "GND" at 5158.16,3406.92 h70.87 r90
  text "GND" at 4241.84,3225.71 h70.87 r270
